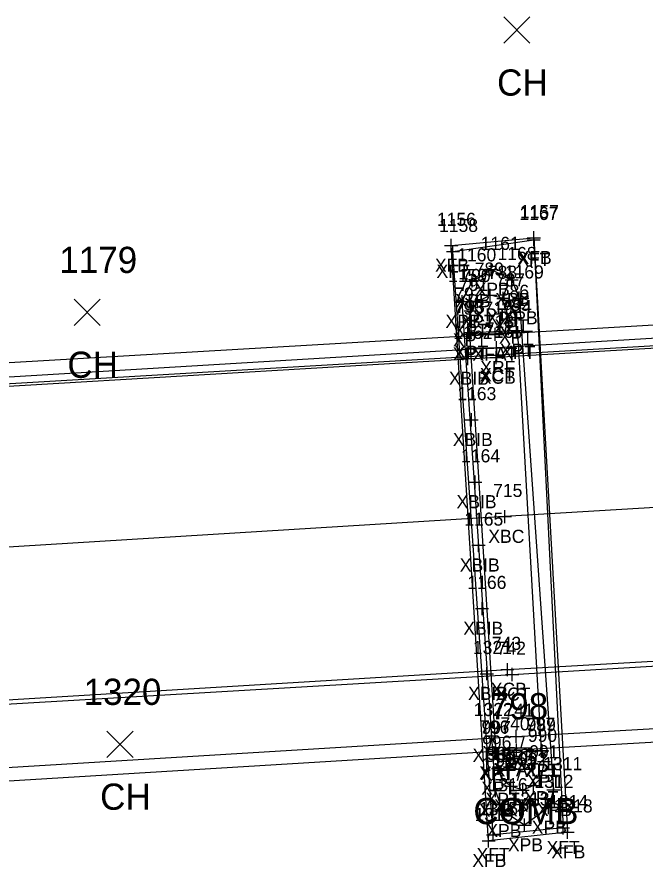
# Model space of a CAD drawing. Extents: x 1715662 to 1717487, y 887396 to 890004.
# Drawn here: x 1716960.4 to 1717008.3, y 888210.8 to 888275.6 of the extents above; entities that cross this region are included whole.
import ezdxf

# ---------------------------------------------------------------- set-up
doc = ezdxf.new("R2010")
doc.units = 0
for name, color, linetype in [('B_A', 7, 'Continuous'), ('B_I', 7, 'Continuous'), ('B_TIC', 7, 'Continuous'), ('BDC', 7, 'Continuous'), ('BELB', 7, 'Continuous'), ('BF', 7, 'Continuous'), ('BFT', 7, 'Continuous'), ('BR', 7, 'Continuous'), ('BSUBM', 7, 'Continuous'), ('L_A', 7, 'Continuous'), ('L_I', 7, 'Continuous'), ('L_TIC', 7, 'Continuous'), ('U_A', 7, 'Continuous'), ('U_I', 7, 'Continuous'), ('UP', 7, 'Continuous')]:
    doc.layers.add(name, color=color, linetype=linetype)

msp = doc.modelspace()

# ---------------------------------------------------------------- linework, layer by layer
at = {"layer": 'B_TIC'}
for p, q in [((1716999.857, 888258.656), (1716999.933, 888258.656)), ((1716999.868, 888258.793), (1716999.944, 888258.793)), ((1716993.563, 888258.21), (1716993.639, 888258.21)), ((1716993.698, 888257.744), (1716993.773, 888257.744)), ((1716996.618, 888256.374), (1716996.694, 888256.374)), ((1716995.153, 888255.5), (1716995.229, 888255.5)), ((1716998.183, 888255.6), (1716998.259, 888255.6)), ((1716996.541, 888254.414), (1716996.617, 888254.414)), ((1716994.393, 888253.93), (1716994.469, 888253.93)), ((1716995.566, 888253.926), (1716995.641, 888253.926)), ((1716997.538, 888254.168), (1716997.614, 888254.168)), ((1716998.745, 888254.197), (1716998.82, 888254.197)), ((1716995.049, 888253.239), (1716995.125, 888253.239)), ((1716998.143, 888253.584), (1716998.218, 888253.584)), ((1716994.974, 888252.512), (1716995.049, 888252.512)), ((1716998.485, 888252.722), (1716998.561, 888252.722)), ((1716994.957, 888251.44), (1716995.033, 888251.44)), ((1716995.078, 888251.568), (1716995.153, 888251.568)), ((1716996.928, 888251.433), (1716997.004, 888251.433)), ((1716998.549, 888251.731), (1716998.624, 888251.731)), ((1716998.658, 888251.565), (1716998.733, 888251.565)), ((1716997.024, 888250.409), (1716997.1, 888250.409)), ((1716997.033, 888249.858), (1716997.109, 888249.858)), ((1716994.822, 888249.583), (1716994.897, 888249.583)), ((1716997.005, 888249.663), (1716997.081, 888249.663)), ((1716995.116, 888244.912), (1716995.191, 888244.912)), ((1716995.404, 888240.168), (1716995.479, 888240.168)), ((1716997.661, 888237.527), (1716997.737, 888237.527)), ((1716995.648, 888235.339), (1716995.723, 888235.339)), ((1716995.914, 888230.512), (1716995.989, 888230.512)), ((1716997.85, 888225.861), (1716997.926, 888225.861)), ((1716996.279, 888225.548), (1716996.355, 888225.548)), ((1716998.219, 888225.489), (1716998.294, 888225.489)), ((1716996.628, 888220.815), (1716996.703, 888220.815)), ((1716998.526, 888220.762), (1716998.601, 888220.762)), ((1716996.973, 888219.484), (1716997.049, 888219.484)), ((1716997.059, 888219.449), (1716997.134, 888219.449)), ((1716998.541, 888219.726), (1716998.616, 888219.726)), ((1717000.457, 888219.692), (1717000.532, 888219.692)), ((1717000.503, 888219.658), (1717000.579, 888219.658)), ((1717000.636, 888218.845), (1717000.712, 888218.845)), ((1716997.134, 888218.322), (1716997.21, 888218.322)), ((1716997.463, 888217.465), (1716997.539, 888217.465)), ((1717000.416, 888217.591), (1717000.492, 888217.591)), ((1716998.12, 888216.963), (1716998.195, 888216.963)), ((1716999.841, 888217.026), (1716999.916, 888217.026)), ((1716996.939, 888216.631), (1716997.015, 888216.631)), ((1716999.022, 888216.666), (1716999.097, 888216.666)), ((1717001.368, 888216.681), (1717001.443, 888216.681)), ((1716997.51, 888215.08), (1716997.585, 888215.08)), ((1717000.975, 888215.331), (1717001.051, 888215.331)), ((1716999.156, 888213.995), (1716999.231, 888213.995)), ((1717002.1, 888213.787), (1717002.175, 888213.787)), ((1716996.753, 888213.25), (1716996.829, 888213.25)), ((1717002.443, 888213.46), (1717002.519, 888213.46)), ((1716996.413, 888212.8), (1716996.489, 888212.8))]:
    msp.add_line(p, q, dxfattribs=at)
for points in [[(1716999.854, 888258.156), (1716999.854, 888259.156)], [(1716999.865, 888258.293), (1716999.865, 888259.293)], [(1716993.56, 888257.71), (1716993.56, 888258.71)], [(1716999.354, 888258.656), (1717000.354, 888258.656)], [(1716999.365, 888258.793), (1717000.365, 888258.793)], [(1716993.06, 888258.21), (1716994.06, 888258.21)], [(1716993.194, 888257.744), (1716994.194, 888257.744)], [(1716993.694, 888257.244), (1716993.694, 888258.244)], [(1716996.115, 888256.374), (1716997.115, 888256.374)], [(1716996.615, 888255.874), (1716996.615, 888256.874)], [(1716995.15, 888255), (1716995.15, 888256)], [(1716998.18, 888255.1), (1716998.18, 888256.1)], [(1716994.65, 888255.5), (1716995.65, 888255.5)], [(1716997.68, 888255.6), (1716998.68, 888255.6)], [(1716994.39, 888253.43), (1716994.39, 888254.43)], [(1716995.562, 888253.426), (1716995.562, 888254.426)], [(1716996.038, 888254.414), (1716997.038, 888254.414)], [(1716996.538, 888253.914), (1716996.538, 888254.914)], [(1716997.535, 888253.668), (1716997.535, 888254.668)], [(1716998.741, 888253.697), (1716998.741, 888254.697)], [(1716993.89, 888253.93), (1716994.89, 888253.93)], [(1716995.046, 888252.739), (1716995.046, 888253.739)], [(1716995.062, 888253.926), (1716996.062, 888253.926)], [(1716997.035, 888254.168), (1716998.035, 888254.168)], [(1716998.139, 888253.084), (1716998.139, 888254.084)], [(1716998.241, 888254.197), (1716999.241, 888254.197)], [(1716994.546, 888253.239), (1716995.546, 888253.239)], [(1716997.639, 888253.584), (1716998.639, 888253.584)], [(1716998.482, 888252.222), (1716998.482, 888253.222)], [(1716994.47, 888252.512), (1716995.47, 888252.512)], [(1716994.97, 888252.012), (1716994.97, 888253.012)], [(1716997.982, 888252.722), (1716998.982, 888252.722)], [(1716994.954, 888250.94), (1716994.954, 888251.94)], [(1716995.074, 888251.068), (1716995.074, 888252.068)], [(1716996.925, 888250.933), (1716996.925, 888251.933)], [(1716998.545, 888251.231), (1716998.545, 888252.231)], [(1716998.654, 888251.065), (1716998.654, 888252.065)], [(1716994.454, 888251.44), (1716995.454, 888251.44)], [(1716994.574, 888251.568), (1716995.574, 888251.568)], [(1716996.425, 888251.433), (1716997.425, 888251.433)], [(1716998.045, 888251.731), (1716999.045, 888251.731)], [(1716998.154, 888251.565), (1716999.154, 888251.565)], [(1716997.021, 888249.909), (1716997.021, 888250.909)], [(1716994.818, 888249.083), (1716994.818, 888250.083)], [(1716996.521, 888250.409), (1716997.521, 888250.409)], [(1716996.53, 888249.858), (1716997.53, 888249.858)], [(1716997.002, 888249.163), (1716997.002, 888250.163)], [(1716997.03, 888249.358), (1716997.03, 888250.358)], [(1716994.318, 888249.583), (1716995.318, 888249.583)], [(1716996.502, 888249.663), (1716997.502, 888249.663)], [(1716995.112, 888244.412), (1716995.112, 888245.412)], [(1716994.612, 888244.912), (1716995.612, 888244.912)], [(1716994.9, 888240.168), (1716995.9, 888240.168)], [(1716995.4, 888239.668), (1716995.4, 888240.668)], [(1716997.158, 888237.527), (1716998.158, 888237.527)], [(1716997.658, 888237.027), (1716997.658, 888238.027)], [(1716995.644, 888234.839), (1716995.644, 888235.839)], [(1716995.144, 888235.339), (1716996.144, 888235.339)], [(1716995.41, 888230.512), (1716996.41, 888230.512)], [(1716995.91, 888230.012), (1716995.91, 888231.012)], [(1716996.276, 888225.048), (1716996.276, 888226.048)], [(1716997.347, 888225.861), (1716998.347, 888225.861)], [(1716997.847, 888225.361), (1716997.847, 888226.361)], [(1716998.215, 888224.989), (1716998.215, 888225.989)], [(1716995.776, 888225.548), (1716996.776, 888225.548)], [(1716997.715, 888225.489), (1716998.715, 888225.489)], [(1716996.624, 888220.315), (1716996.624, 888221.315)], [(1716996.124, 888220.815), (1716997.124, 888220.815)], [(1716998.022, 888220.762), (1716999.022, 888220.762)], [(1716998.522, 888220.262), (1716998.522, 888221.262)], [(1716998.537, 888219.226), (1716998.537, 888220.226)], [(1717000.453, 888219.192), (1717000.453, 888220.192)], [(1717000.5, 888219.158), (1717000.5, 888220.158)], [(1716996.47, 888219.484), (1716997.47, 888219.484)], [(1716996.555, 888219.449), (1716997.555, 888219.449)], [(1716996.97, 888218.984), (1716996.97, 888219.984)], [(1716997.055, 888218.949), (1716997.055, 888219.949)], [(1716998.037, 888219.726), (1716999.037, 888219.726)], [(1716999.953, 888219.692), (1717000.953, 888219.692)], [(1717000, 888219.658), (1717001, 888219.658)], [(1717000.633, 888218.345), (1717000.633, 888219.345)], [(1716997.131, 888217.822), (1716997.131, 888218.822)], [(1717000.133, 888218.845), (1717001.133, 888218.845)], [(1716996.631, 888218.322), (1716997.631, 888218.322)], [(1717000.413, 888217.091), (1717000.413, 888218.091)], [(1716996.96, 888217.465), (1716997.96, 888217.465)], [(1716997.46, 888216.965), (1716997.46, 888217.965)], [(1716998.116, 888216.463), (1716998.116, 888217.463)], [(1716999.837, 888216.526), (1716999.837, 888217.526)], [(1716999.913, 888217.591), (1717000.913, 888217.591)], [(1716996.936, 888216.131), (1716996.936, 888217.131)], [(1716997.616, 888216.963), (1716998.616, 888216.963)], [(1716999.018, 888216.166), (1716999.018, 888217.166)], [(1716999.337, 888217.026), (1717000.337, 888217.026)], [(1717001.364, 888216.181), (1717001.364, 888217.181)], [(1716996.436, 888216.631), (1716997.436, 888216.631)], [(1716998.518, 888216.666), (1716999.518, 888216.666)], [(1717000.864, 888216.681), (1717001.864, 888216.681)], [(1716997.506, 888214.58), (1716997.506, 888215.58)], [(1717000.972, 888214.831), (1717000.972, 888215.831)], [(1716997.006, 888215.08), (1716998.006, 888215.08)], [(1717000.472, 888215.331), (1717001.472, 888215.331)], [(1716999.152, 888213.495), (1716999.152, 888214.495)], [(1717002.096, 888213.287), (1717002.096, 888214.287)], [(1716996.75, 888212.75), (1716996.75, 888213.75)], [(1716998.652, 888213.995), (1716999.652, 888213.995)], [(1717001.596, 888213.787), (1717002.596, 888213.787)], [(1717002.44, 888212.96), (1717002.44, 888213.96)], [(1716996.25, 888213.25), (1716997.25, 888213.25)], [(1716996.41, 888212.3), (1716996.41, 888213.3)], [(1717001.94, 888213.46), (1717002.94, 888213.46)], [(1716995.91, 888212.8), (1716996.91, 888212.8)]]:
    msp.add_lwpolyline(points, dxfattribs=at)
at = {"layer": 'BDC'}
for points in [[(1717176.589, 888262.234), (1717176.877, 888260.812), (1717116.829, 888257.088), (1717056.7, 888253.344), (1716997.03, 888249.858), (1716936.998, 888246.313), (1716877.496, 888242.928), (1716877.301, 888244.49)], [(1717176.976, 888262.024), (1717176.866, 888260.514), (1717116.827, 888256.946), (1717056.83, 888253.148), (1716997.002, 888249.663), (1716937.062, 888246.095), (1716877.423, 888242.56)], [(1716878.985, 888212.69), (1716878.754, 888218.609), (1716938.217, 888221.984), (1716998.215, 888225.489), (1717058.321, 888229.074), (1717118.074, 888232.734), (1717177.978, 888236.214), (1717178.104, 888235.65), (1717178.633, 888230.445)], [(1716878.76, 888218.785), (1716938.254, 888222.245), (1716997.847, 888225.861), (1717058.278, 888229.335), (1717118.147, 888232.862), (1717177.913, 888236.497)]]:
    msp.add_lwpolyline(points, dxfattribs=at)
at = {"layer": 'BELB'}
msp.add_lwpolyline([(1717176.82, 888248.242), (1717117.599, 888244.664), (1717057.58, 888241.128), (1716997.658, 888237.527), (1716937.868, 888233.85), (1716878.264, 888230.514)], dxfattribs=at)
at = {"layer": 'BF'}
for points in [[(1717176.589, 888262.234), (1717116.538, 888258.636), (1717056.61, 888254.944), (1716996.925, 888251.433), (1716937.102, 888247.945), (1716877.301, 888244.49)], [(1716878.985, 888212.69), (1716938.928, 888216.097), (1716998.537, 888219.726), (1717058.79, 888223.18), (1717118.388, 888226.857), (1717178.633, 888230.445)]]:
    msp.add_lwpolyline(points, dxfattribs=at)
at = {"layer": 'BFT'}
for points in [[(1716993.56, 888258.21), (1716999.865, 888258.793), (1717002.44, 888213.46), (1716996.41, 888212.8)], [(1716993.694, 888257.744), (1716999.854, 888258.656), (1717002.096, 888213.787), (1716996.75, 888213.25)], [(1716996.41, 888212.8), (1716993.56, 888258.21)], [(1716996.75, 888213.25), (1716993.694, 888257.744)]]:
    msp.add_lwpolyline(points, dxfattribs=at)
at = {"layer": 'BR'}
for points in [[(1717175.997, 888261.982), (1717175.88, 888261.141), (1717117.062, 888257.612), (1717056.557, 888253.997), (1716997.021, 888250.409), (1716936.966, 888246.784), (1716878.141, 888243.386), (1716877.962, 888244.411)], [(1716879.623, 888212.902), (1716879.679, 888213.775), (1716938.703, 888217.127), (1716998.522, 888220.762), (1717058.504, 888224.208), (1717118.654, 888227.867), (1717177.581, 888231.531), (1717177.859, 888230.636)]]:
    msp.add_lwpolyline(points, dxfattribs=at)
at = {"layer": 'BSUBM'}
for points in [[(1716994.39, 888253.93), (1716995.15, 888255.5), (1716996.615, 888256.374), (1716998.18, 888255.6), (1716998.741, 888254.197), (1717001.364, 888216.681), (1717000.972, 888215.331), (1716999.152, 888213.995), (1716997.506, 888215.08), (1716996.936, 888216.631)], [(1716998.545, 888251.731), (1716998.482, 888252.722), (1716998.139, 888253.584), (1716997.535, 888254.168), (1716996.538, 888254.414), (1716995.562, 888253.926), (1716995.046, 888253.239), (1716994.97, 888252.512), (1716995.074, 888251.568)], [(1716996.936, 888216.631), (1716994.39, 888253.93)], [(1716998.654, 888251.565), (1716994.954, 888251.44), (1716996.97, 888219.484), (1717000.453, 888219.692)], [(1716995.074, 888251.568), (1716998.545, 888251.731)], [(1717000.453, 888219.692), (1716998.654, 888251.565)], [(1717000.5, 888219.658), (1717000.633, 888218.845), (1717000.413, 888217.591), (1716999.837, 888217.026), (1716999.018, 888216.666), (1716998.116, 888216.963), (1716997.46, 888217.465), (1716997.131, 888218.322), (1716997.055, 888219.449)], [(1716997.055, 888219.449), (1717000.5, 888219.658)]]:
    msp.add_lwpolyline(points, dxfattribs=at)
at = {"layer": 'L_TIC'}
for points in [[(1716997.572, 888273.643), (1716999.572, 888275.643)], [(1716999.572, 888273.643), (1716997.572, 888275.643)], [(1716964.782, 888252.114), (1716966.782, 888254.114)], [(1716966.782, 888252.114), (1716964.782, 888254.114)], [(1716967.279, 888219.164), (1716969.279, 888221.164)], [(1716969.279, 888219.164), (1716967.279, 888221.164)]]:
    msp.add_lwpolyline(points, dxfattribs=at)
at = {"layer": 'UP'}
for p, q in [((1716999.111, 888220.731), (1716998.861, 888219.898)), ((1716998.027, 888218.231), (1716998.027, 888219.898)), ((1716998.027, 888219.898), (1716999.694, 888219.898)), ((1716999.694, 888219.898), (1716999.694, 888218.231)), ((1716998.861, 888219.065), (1716998.861, 888219.065)), ((1716999.694, 888218.231), (1716998.027, 888218.231)), ((1716998.611, 888217.398), (1716998.861, 888218.231))]:
    msp.add_line(p, q, dxfattribs=at)
msp.add_circle((1716998.861, 888219.065), 0.833, dxfattribs=at)

# ---------------------------------------------------------------- texts
at = {"layer": 'B_A'}
for s, p in [('XFT', (1716998.598, 888256.656)), ('XFB', (1716998.625, 888256.793)), ('XFB', (1716992.32, 888256.21)), ('XFT', (1716992.439, 888255.744)), ('XPB', (1716995.351, 888254.374)), ('XPB', (1716993.886, 888253.5)), ('XPB', (1716996.916, 888253.6)), ('XPT', (1716995.258, 888252.414)), ('XPT', (1716996.255, 888252.168)), ('XPB', (1716997.477, 888252.197)), ('XPB', (1716993.126, 888251.93)), ('XPT', (1716994.283, 888251.926)), ('XPT', (1716996.86, 888251.584)), ('XPT', (1716993.766, 888251.239)), ('XPT', (1716993.691, 888250.512)), ('XPT', (1716997.202, 888250.722)), ('XPT', (1716993.795, 888249.568)), ('XPT', (1716997.266, 888249.731)), ('XPT', (1716997.375, 888249.565)), ('XPT', (1716993.674, 888249.44)), ('XFAT', (1716995.181, 888249.433)), ('XRF', (1716995.781, 888248.409)), ('XBIB', (1716993.389, 888247.583)), ('XCB', (1716995.738, 888247.663)), ('XCT', (1716995.75, 888247.858)), ('XBIB', (1716993.683, 888242.912)), ('XBIB', (1716993.971, 888238.168)), ('XBC', (1716996.394, 888235.527)), ('XBIB', (1716994.215, 888233.339)), ('XBIB', (1716994.481, 888228.512)), ('XBIB', (1716994.847, 888223.548)), ('XCB', (1716996.583, 888223.861)), ('XCT', (1716996.936, 888223.489)), ('XBIB', (1716995.195, 888218.815)), ('XRF', (1716997.282, 888218.762)), ('XFAT', (1716996.793, 888217.726)), ('XPT', (1716995.69, 888217.484)), ('XPT', (1716995.776, 888217.449)), ('XPT', (1716999.174, 888217.692)), ('XPT', (1716999.22, 888217.658)), ('XPT', (1716999.353, 888216.845)), ('XPT', (1716995.851, 888216.322)), ('XPT', (1716996.18, 888215.465)), ('XPT', (1716999.133, 888215.591)), ('XPB', (1716995.672, 888214.631)), ('XPT', (1716996.837, 888214.963)), ('XPT', (1716997.739, 888214.666)), ('XPT', (1716998.558, 888215.026)), ('XPB', (1717000.101, 888214.681)), ('XPB', (1716999.708, 888213.331)), ('XPB', (1716996.243, 888213.08)), ('XPB', (1716997.889, 888211.995)), ('XFT', (1716995.494, 888211.25)), ('XFT', (1717000.84, 888211.787)), ('XFB', (1717001.2, 888211.46)), ('XFB', (1716995.17, 888210.8))]:
    msp.add_text(s, height=1, dxfattribs=at).set_placement(p)
at = {"layer": 'B_I'}
for s, p in [('1167', (1716998.767, 888260.156)), ('1157', (1716998.802, 888260.293)), ('1156', (1716992.469, 888259.71)), ('1158', (1716992.631, 888259.244)), ('1161', (1716995.812, 888257.874)), ('1160', (1716994.02, 888257)), ('1168', (1716997.093, 888257.1)), ('1159', (1716993.323, 888255.43)), ('790', (1716994.338, 888255.426)), ('789', (1716995.353, 888255.914)), ('788', (1716996.354, 888255.668)), ('1169', (1716997.651, 888255.697)), ('791', (1716994.148, 888254.739)), ('787', (1716996.958, 888255.084)), ('792', (1716993.789, 888254.012)), ('786', (1716997.273, 888254.222)), ('795', (1716993.772, 888252.94)), ('793', (1716993.893, 888253.068)), ('719', (1716996.023, 888252.933)), ('785', (1716997.364, 888253.231)), ('794', (1716997.473, 888253.065)), ('718', (1716996.123, 888251.909)), ('1162', (1716993.732, 888251.083)), ('716', (1716996.076, 888251.163)), ('717', (1716996.132, 888251.358)), ('1163', (1716994.026, 888246.412)), ('1164', (1716994.314, 888241.668)), ('715', (1716996.76, 888239.027)), ('1165', (1716994.557, 888236.839)), ('1166', (1716994.796, 888232.012)), ('1321', (1716995.213, 888227.048)), ('743', (1716996.666, 888227.361)), ('742', (1716997.034, 888226.989)), ('1322', (1716995.278, 888222.315)), ('741', (1716997.625, 888222.262)), ('796', (1716995.761, 888220.984)), ('997', (1716995.874, 888220.949)), ('740', (1716997.313, 888221.226)), ('797', (1716999.272, 888221.192)), ('989', (1716999.315, 888221.158)), ('990', (1716999.408, 888220.345)), ('996', (1716995.922, 888219.822)), ('991', (1716999.515, 888219.091)), ('995', (1716996.278, 888218.965)), ('994', (1716996.935, 888218.463)), ('992', (1716998.656, 888218.526)), ('1317', (1716995.873, 888218.131)), ('993', (1716997.837, 888218.166)), ('1311', (1717000.585, 888218.181)), ('1316', (1716996.416, 888216.58)), ('1312', (1716999.909, 888216.831)), ('1313', (1716998.089, 888215.495)), ('1314', (1717001.033, 888215.287)), ('1315', (1716995.687, 888214.75)), ('1318', (1717001.377, 888214.96)), ('1319', (1716995.343, 888214.3))]:
    msp.add_text(s, height=1, dxfattribs=at).set_placement(p)
at = {"layer": 'L_A'}
for p in [(1716997.06, 888269.643), (1716964.27, 888248.114), (1716966.767, 888215.164)]:
    msp.add_text('CH', height=2, dxfattribs=at).set_placement(p)
at = {"layer": 'L_I'}
for s, p in [('1179', (1716963.648, 888256.114)), ('1320', (1716965.499, 888223.164))]:
    msp.add_text(s, height=2, dxfattribs=at).set_placement(p)
at = {"layer": 'U_A'}
msp.add_text('COMB', height=2, dxfattribs=at).set_placement((1716995.247, 888214.065))
at = {"layer": 'U_I'}
msp.add_text('798', height=2, dxfattribs=at).set_placement((1716996.499, 888222.065))

doc.saveas('drawing.dxf')
